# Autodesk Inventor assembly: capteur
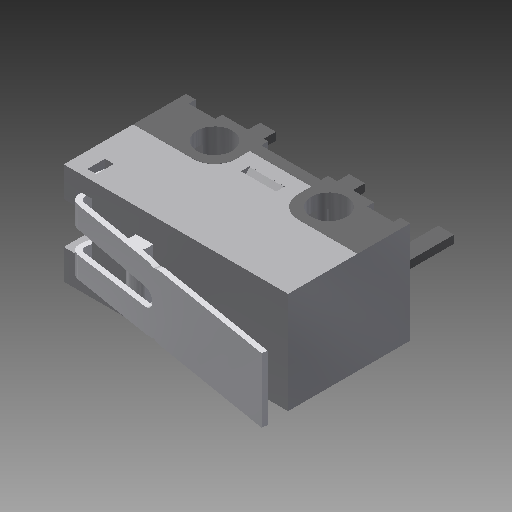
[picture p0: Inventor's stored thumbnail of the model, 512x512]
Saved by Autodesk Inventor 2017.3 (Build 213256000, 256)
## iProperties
Created: 2007-12
Part Number: capteur
Material: Générique
Document SubType Name: Assembly
Designer: ficho
Author: ficho
Sending System: SolidWorks 2009
Last Author: christophe
Last Saved: 2011-02-10
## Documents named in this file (5)
- G:\travail\année 2019-2020\réforme\toussaint\Serrure biométrique SET\Documentations_pedagogique\Modelisation_Solidworks\capteur.iam
- G:\travail\année 2019-2020\réforme\toussaint\Serrure biométrique SET\Documentations_pedagogique\Modelisation_Solidworks\piece26.ipt
- G:\travail\année 2019-2020\réforme\toussaint\Serrure biométrique SET\Documentations_pedagogique\Modelisation_Solidworks\piece 28.ipt
- G:\travail\année 2019-2020\réforme\toussaint\Serrure biométrique SET\Documentations_pedagogique\Modelisation_Solidworks\piece27.ipt
- G:\travail\année 2019-2020\réforme\toussaint\Serrure biométrique SET\Documentations_pedagogique\Modelisation_Solidworks\piece29.ipt
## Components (4 placed, 4 different names)
1. piece26:1
2. piece 28:1
3. piece27:2
4. piece29:1
